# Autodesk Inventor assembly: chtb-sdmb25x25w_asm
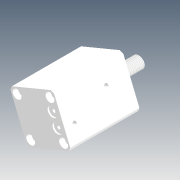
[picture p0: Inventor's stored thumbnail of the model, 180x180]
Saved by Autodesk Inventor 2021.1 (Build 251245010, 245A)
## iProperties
Company: Microsoft
Created: 2018-05
Part Number: chtb-sdmb25x25w_asm
Description: STEP AP214
Document SubType Name: Assembly
Designer: user
Title: chtb-sdmb25x25w_asm.STEP
Author: Windows
Revision Number: ÈÎºÎ
Sending System: SolidWorks 2015
Preprocessor: SwSTEP 2.0
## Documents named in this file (4)
- D:\Vault_2016\Projekty\Clamptek\Hydraulic\CHTB\CHTB-25\Inventor\chtb-sdmb25x25w\chtb-sdmb25x25w_asm.iam
- D:\Vault_2016\Projekty\Clamptek\Hydraulic\CHTB\CHTB-25\Inventor\chtb-sdmb25x25w\CHTB-25QG.ipt
- D:\Vault_2016\Projekty\Clamptek\Hydraulic\CHTB\CHTB-25\Inventor\chtb-sdmb25x25w\CHTB-SDMB25X25NBT.ipt
- D:\Vault_2016\Projekty\Clamptek\Hydraulic\CHTB\CHTB-25\Inventor\chtb-sdmb25x25w\CHTB-SDMB25X25WHSG.ipt
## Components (3 placed, 3 different names)
1. CHTB-25QG_1
2. CHTB-SDMB25X25NBT_2
3. CHTB-SDMB25X25WHSG_3
